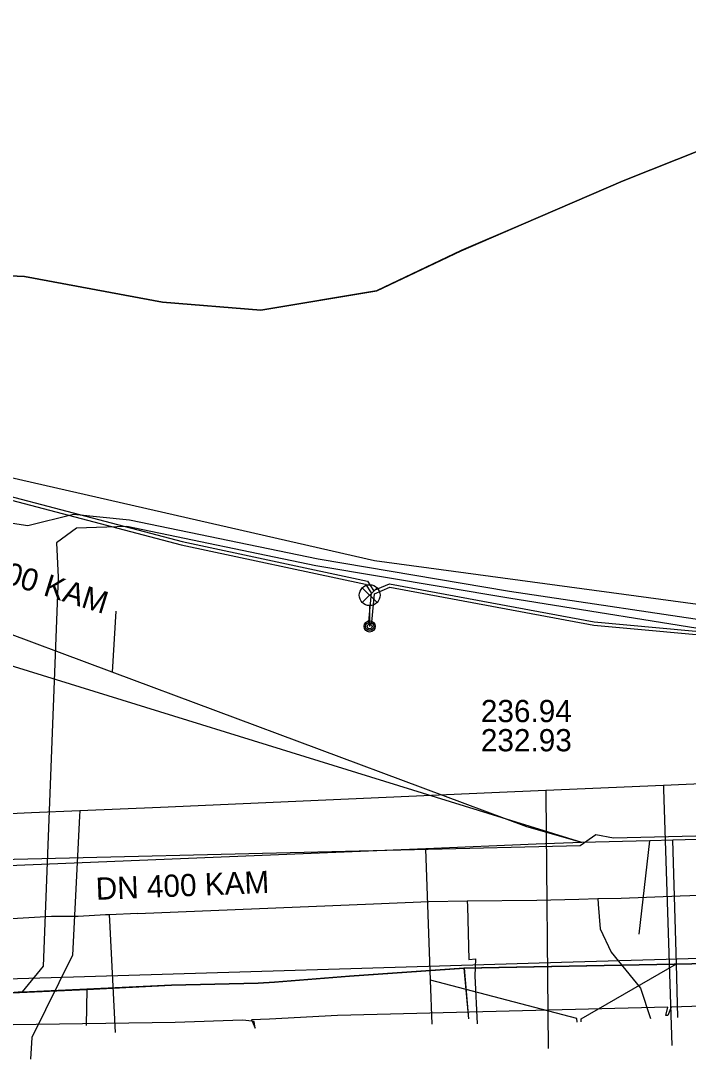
# Model space of a CAD drawing. Extents: x -595540 to -593988, y -1160850 to -1159202.
# Drawn here: x -594932.45 to -594908.44, y -1160782.42 to -1160745.06 of the extents above; entities that cross this region are included whole.
import ezdxf

# ---------------------------------------------------------------- set-up
doc = ezdxf.new("R2010")
doc.units = 0
for name, color, linetype in [('BKOM-ODVODNENI_trasa sítě', 7, 'Continuous'), ('BVK-JEDNOTNA_popisy', 7, 'Continuous'), ('BVK-JEDNOTNA_trasa sítě', 7, 'Continuous'), ('BVK-KANALIZACE_ vyřazená trasa sítě', 7, 'Continuous'), ('BVK-VODOVOD_trasa sítě', 7, 'Continuous'), ('BVK-VODOVOD_trasa zrušené sítě', 7, 'Continuous'), ('CETIN_kabel podzemní', 7, 'Continuous'), ('DESTOVA_trasa neprovozované sítě', 7, 'Continuous'), ('DSP-SDEL-VODAFONE_kabel', 7, 'Continuous'), ('EON-NN_kabel', 7, 'Continuous'), ('EON-VN_kabel', 7, 'Continuous'), ('INNOGY-STL_trasa sítě', 7, 'Continuous'), ('JEDNOTNA_trasa neprovozované sítě', 7, 'Continuous'), ('TSB_kabel VO', 7, 'Continuous'), ('TSB_lampy VO', 7, 'Continuous')]:
    doc.layers.add(name, color=color, linetype=linetype)

msp = doc.modelspace()

# ---------------------------------------------------------------- linework, layer by layer
at = {"layer": 'BKOM-ODVODNENI_trasa sítě'}
msp.add_lwpolyline([(-594910.2, -1160777.92), (-594909.817, -1160774.559)], dxfattribs=at)
at = {"layer": 'BVK-JEDNOTNA_popisy'}
msp.add_line((-594915.9, -1160770.417), (-594915.9, -1160770.417), dxfattribs=at)
at = {"layer": 'BVK-JEDNOTNA_trasa sítě'}
for points in [[(-594912.273, -1160774.624), (-594938.769, -1160766.417), (-594951.138, -1160762.587), (-594956.75, -1160760.85)], [(-594869.804, -1160773.507), (-594873.738, -1160773.61), (-594874.61, -1160773.633), (-594878.19, -1160773.728), (-594884.02, -1160773.881), (-594885.041, -1160773.908), (-594892.812, -1160774.112), (-594903.717, -1160774.399), (-594908.994, -1160774.538), (-594909.817, -1160774.559), (-594912.273, -1160774.624)], [(-594912.273, -1160774.624), (-594913.908, -1160774.683), (-594917.874, -1160774.85), (-594935.248, -1160775.554), (-594938.697, -1160775.692), (-594939.571, -1160775.728), (-594941.692, -1160775.813)]]:
    msp.add_lwpolyline(points, dxfattribs=at)
at = {"layer": 'BVK-KANALIZACE_ vyřazená trasa sítě'}
msp.add_line((-594929.03, -1160766.3), (-594929.167, -1160768.492), dxfattribs=at)
for points in [[(-594912.273, -1160774.624), (-594914.244, -1160774.053), (-594929.167, -1160768.492), (-594938.554, -1160764.996), (-594948.512, -1160761.285), (-594951.232, -1160760.272)], [(-594869.699, -1160773.46), (-594911.123, -1160774.466), (-594911.762, -1160774.34)], [(-594911.762, -1160774.34), (-594912.332, -1160774.739), (-594936.179, -1160775.32)]]:
    msp.add_lwpolyline(points, dxfattribs=at)
at = {"layer": 'BVK-VODOVOD_trasa sítě'}
for points in [[(-594875.78, -1160771.11), (-594879.52, -1160771.27), (-594880.35, -1160771.31), (-594885.83, -1160771.55), (-594891.69, -1160771.8), (-594894.1, -1160771.91), (-594896.86, -1160772.03), (-594897.67, -1160772.06), (-594903.61, -1160772.32), (-594909.33, -1160772.57), (-594913.56, -1160772.75), (-594915.51, -1160772.84), (-594921.48, -1160773.1), (-594927.42, -1160773.36), (-594930.33, -1160773.48), (-594932.06, -1160773.56), (-594935.46, -1160773.71), (-594935.76, -1160773.72)], [(-594913.56, -1160772.75), (-594913.56, -1160772.9), (-594913.48, -1160782.03)], [(-594909.33, -1160772.57), (-594909.33, -1160772.7), (-594909.03, -1160781.93)], [(-594930.33, -1160773.48), (-594930.34, -1160773.67), (-594930.59, -1160778.67), (-594932.052, -1160781.638), (-594932.1, -1160782.418)]]:
    msp.add_lwpolyline(points, dxfattribs=at)
at = {"layer": 'BVK-VODOVOD_trasa zrušené sítě'}
msp.add_lwpolyline([(-594937.054, -1160779.34), (-594937.071, -1160779.648), (-594936.613, -1160779.634), (-594931.361, -1160779.477), (-594913.001, -1160778.927), (-594909.231, -1160778.814), (-594895.813, -1160778.413), (-594892.17, -1160778.304), (-594879.821, -1160777.934), (-594879.469, -1160777.923), (-594875.52, -1160777.778), (-594865.11, -1160777.493), (-594857.269, -1160777.258), (-594850.43, -1160777.053), (-594849.217, -1160777.017), (-594840.994, -1160776.771), (-594839.675, -1160776.732), (-594826.216, -1160776.329), (-594818.306, -1160776.092), (-594815.474, -1160776.007), (-594804.299, -1160775.672), (-594801.425, -1160775.476), (-594800.948, -1160775.379), (-594799.195, -1160774.938)], dxfattribs=at)
at = {"layer": 'CETIN_kabel podzemní'}
for points in [[(-594895.23, -1160720.37), (-594899.75, -1160734.09), (-594904.07, -1160746.78), (-594904.7, -1160747.94), (-594905.92, -1160748.89), (-594910.78, -1160750.82), (-594914.36, -1160752.37), (-594916.61, -1160753.33), (-594919.65, -1160754.78), (-594923.82, -1160755.47), (-594927.35, -1160755.18), (-594932.31, -1160754.26), (-594936.32, -1160754.08), (-594936.74, -1160754.26), (-594937.69, -1160756.31), (-594938.49, -1160759.33), (-594938.98, -1160760.4), (-594939.13, -1160760.57), (-594944.88, -1160758.83), (-594949.88, -1160756.96), (-594958.59, -1160753.03)], [(-594907.05, -1160778.96), (-594916.51, -1160779.14)], [(-594916.51, -1160779.14), (-594920.62, -1160779.43), (-594923.32, -1160779.65), (-594923.91, -1160779.68), (-594927.03, -1160779.75), (-594930.07, -1160779.9)], [(-594916.51, -1160779.14), (-594916.34, -1160780.97)], [(-594930.07, -1160779.9), (-594936.26, -1160780.19), (-594938.27, -1160779.7), (-594941.61, -1160779.83), (-594944.66, -1160779.93)], [(-594930.07, -1160779.9), (-594930.1, -1160781.2)]]:
    msp.add_lwpolyline(points, dxfattribs=at)
at = {"layer": 'DESTOVA_trasa neprovozované sítě'}
msp.add_line((-594910.2, -1160777.92), (-594909.817, -1160774.559), dxfattribs=at)
for points in [[(-594912.295, -1160781.078), (-594912.293, -1160780.959), (-594908.866, -1160778.981)], [(-594912.438, -1160781.081), (-594912.45, -1160780.95), (-594917.71, -1160779.574)]]:
    msp.add_lwpolyline(points, dxfattribs=at)
at = {"layer": 'DSP-SDEL-VODAFONE_kabel'}
for p, q in [((-594923.32, -1160779.645), (-594920.622, -1160779.426)), ((-594916.505, -1160779.14), (-594916.354, -1160780.821)), ((-594927.031, -1160779.755), (-594923.907, -1160779.676)), ((-594923.907, -1160779.676), (-594923.32, -1160779.645)), ((-594930.068, -1160779.904), (-594930.102, -1160781.2))]:
    msp.add_line(p, q, dxfattribs=at)
for points in [[(-594938.488, -1160759.33), (-594937.687, -1160756.308), (-594936.74, -1160754.258), (-594936.322, -1160754.083), (-594932.311, -1160754.259), (-594927.352, -1160755.184), (-594923.818, -1160755.468), (-594919.646, -1160754.777), (-594916.614, -1160753.334), (-594914.364, -1160752.368), (-594910.783, -1160750.823), (-594905.922, -1160748.887), (-594904.703, -1160747.939), (-594904.067, -1160746.78), (-594899.752, -1160734.092), (-594895.232, -1160720.373)], [(-594920.622, -1160779.426), (-594916.505, -1160779.14), (-594907.052, -1160778.961), (-594904.043, -1160778.964), (-594900.222, -1160778.658), (-594895.653, -1160778.692), (-594891.744, -1160778.513), (-594881.932, -1160778.17)], [(-594941.607, -1160779.832), (-594938.271, -1160779.704), (-594936.26, -1160780.191), (-594930.068, -1160779.904), (-594927.031, -1160779.755)]]:
    msp.add_lwpolyline(points, dxfattribs=at)
at = {"layer": 'EON-NN_kabel'}
for points in [[(-594924.124, -1160781.052), (-594924.47, -1160781.01), (-594926.89, -1160781.1), (-594936.071, -1160781.233), (-594936.058, -1160781.664), (-594936.258, -1160781.67), (-594936.458, -1160781.676), (-594936.471, -1160781.238), (-594936.58, -1160781.24), (-594939.38, -1160781.255), (-594939.43, -1160779.153), (-594940.36, -1160772.875), (-594940.37, -1160770.411), (-594941.236, -1160769.85), (-594941.104, -1160769.351), (-594939.076, -1160763.186), (-594938.234, -1160760.23), (-594938.802, -1160760.034), (-594944.719, -1160757.99), (-594947.541, -1160756.987), (-594949.413, -1160756.455), (-594955.16, -1160753.921), (-594955.839, -1160753.578), (-594955.533, -1160752.952)], [(-594906.59, -1160766.27), (-594919.73, -1160764.49), (-594933.23, -1160761.41), (-594938.672, -1160759.656), (-594944.586, -1160757.612), (-594947.992, -1160756.462), (-594947.601, -1160755.445), (-594948.103, -1160755.221), (-594948.143, -1160755.335), (-594948.256, -1160755.622), (-594948.08, -1160755.71), (-594948.345, -1160756.368), (-594949.277, -1160756.078), (-594954.28, -1160753.872), (-594954.252, -1160753.525), (-594954.579, -1160753.735), (-594954.989, -1160753.56), (-594955.306, -1160753.399), (-594955.176, -1160753.133)], [(-594874.32, -1160779.5), (-594875.033, -1160779.44), (-594879.561, -1160779.511), (-594879.602, -1160779.741), (-594879.629, -1160779.95), (-594879.702, -1160779.95), (-594879.683, -1160779.514), (-594894.741, -1160779.94), (-594894.5, -1160780.366), (-594894.597, -1160780.37), (-594894.861, -1160779.944), (-594901.474, -1160780.295), (-594901.528, -1160780.588), (-594901.595, -1160780.596), (-594901.593, -1160780.3), (-594909.052, -1160780.543), (-594909.179, -1160780.84), (-594909.247, -1160780.842), (-594909.176, -1160780.546), (-594921.055, -1160780.846), (-594923.501, -1160780.971), (-594924.146, -1160780.999), (-594924.124, -1160781.052)], [(-594924.124, -1160781.052), (-594924.02, -1160781.301), (-594924.06, -1160781.06), (-594924.124, -1160781.052)]]:
    msp.add_lwpolyline(points, dxfattribs=at)
at = {"layer": 'EON-VN_kabel'}
for points in [[(-594936.2, -1160762.61), (-594932.2, -1160763.22), (-594930.55, -1160762.81), (-594928.54, -1160763.01), (-594921.75, -1160764.42), (-594914.87, -1160765.58), (-594906.82, -1160766.78), (-594899.34, -1160767.22), (-594889.38, -1160767.35), (-594875.36, -1160766.99)], [(-594875.39, -1160767.22), (-594889.34, -1160767.51), (-594899.32, -1160767.54), (-594906.82, -1160767.13), (-594914.89, -1160765.83), (-594921.84, -1160764.67), (-594928.63, -1160763.25), (-594930.45, -1160763.32), (-594931.16, -1160763.84), (-594931.105, -1160765.083), (-594931.649, -1160779.07), (-594932.397, -1160779.995), (-594936.47, -1160780.325)]]:
    msp.add_lwpolyline(points, dxfattribs=at)
at = {"layer": 'INNOGY-STL_trasa sítě'}
for points in [[(-594928.245, -1160777.18), (-594919.762, -1160776.826), (-594917.777, -1160776.749), (-594916.389, -1160776.724), (-594913.889, -1160776.699), (-594912.378, -1160776.66), (-594911.693, -1160776.642), (-594910.858, -1160776.621), (-594908.726, -1160776.537), (-594908.385, -1160776.528), (-594905.624, -1160776.458), (-594904.839, -1160777.239), (-594904.046, -1160777.189), (-594902.065, -1160777.141), (-594900.409, -1160777.053), (-594896.121, -1160776.923), (-594892.145, -1160776.735), (-594891.857, -1160776.721), (-594886.017, -1160776.442), (-594884.037, -1160776.363), (-594882.602, -1160776.298), (-594882.305, -1160776.287), (-594881.235, -1160776.269), (-594877.615, -1160776.166)], [(-594916.389, -1160776.724), (-594916.384, -1160776.924), (-594916.338, -1160778.831), (-594916.086, -1160778.809)], [(-594911.693, -1160776.642), (-594911.677, -1160776.841), (-594911.607, -1160777.724), (-594911.215, -1160778.564), (-594910.162, -1160779.864), (-594909.795, -1160780.955)], [(-594928.245, -1160777.18), (-594929.267, -1160777.223), (-594929.403, -1160777.228), (-594930.379, -1160777.284), (-594931.097, -1160777.289), (-594931.343, -1160777.288), (-594932.969, -1160777.384), (-594933.372, -1160777.377), (-594935.337, -1160777.439), (-594935.642, -1160777.439)], [(-594929.267, -1160777.223), (-594929.257, -1160777.423), (-594929.051, -1160781.453)], [(-594916.02, -1160781.14), (-594916.11, -1160779.42), (-594916.086, -1160778.809)]]:
    msp.add_lwpolyline(points, dxfattribs=at)
at = {"layer": 'JEDNOTNA_trasa neprovozované sítě'}
for points in [[(-594908.811, -1160780.912), (-594908.866, -1160778.981), (-594908.994, -1160774.538)], [(-594917.655, -1160781.16), (-594917.71, -1160779.574), (-594917.874, -1160774.85)]]:
    msp.add_lwpolyline(points, dxfattribs=at)
at = {"layer": 'TSB_kabel VO'}
for points in [[(-594960.962, -1160749.196), (-594961.234, -1160749.502), (-594961.632, -1160750.685), (-594961.412, -1160751.238), (-594955.624, -1160754.466), (-594947.358, -1160757.854), (-594945.703, -1160758.452), (-594944.394, -1160758.762), (-594937.883, -1160760.881), (-594937.508, -1160760.941), (-594926.646, -1160763.792), (-594919.973, -1160765.217), (-594919.757, -1160765.555), (-594919.187, -1160765.318), (-594911.822, -1160766.681), (-594901.376, -1160767.64), (-594895.647, -1160767.84), (-594883.2, -1160768.76), (-594881.163, -1160768.61), (-594878.423, -1160768.506), (-594877.437, -1160767.931)], [(-594961.508, -1160751.322), (-594955.676, -1160754.574), (-594947.402, -1160757.966), (-594945.737, -1160758.568), (-594944.426, -1160758.878), (-594938.129, -1160760.927), (-594937.968, -1160760.979), (-594938.275, -1160762.29), (-594938.335, -1160762.438), (-594938.165, -1160762.35), (-594937.852, -1160761.007), (-594937.532, -1160761.059), (-594926.674, -1160763.908), (-594920.047, -1160765.323), (-594919.842, -1160765.645), (-594919.941, -1160766.684), (-594919.894, -1160766.83), (-594919.821, -1160766.695), (-594919.724, -1160765.672), (-594919.173, -1160765.442), (-594911.838, -1160766.799), (-594901.445, -1160767.754)]]:
    msp.add_lwpolyline(points, dxfattribs=at)
at = {"layer": 'TSB_lampy VO'}
for p, q in [((-594920.165, -1160765.99), (-594919.635, -1160765.46)), ((-594920.165, -1160765.46), (-594919.635, -1160765.99)), ((-594920.165, -1160765.99), (-594919.635, -1160765.46)), ((-594920.165, -1160765.46), (-594919.635, -1160765.99)), ((-594919.9, -1160766.1), (-594919.9, -1160766.85)), ((-594919.9, -1160766.1), (-594919.9, -1160766.85))]:
    msp.add_line(p, q, dxfattribs=at)
for centre, radius in [((-594919.9, -1160765.725), 0.375), ((-594919.9, -1160765.725), 0.375), ((-594919.9, -1160766.85), 0.2), ((-594919.9, -1160766.85), 0.2), ((-594919.9, -1160766.85), 0.145), ((-594919.9, -1160766.85), 0.145), ((-594919.9, -1160766.85), 0.0876), ((-594919.9, -1160766.85), 0.0876)]:
    msp.add_circle(centre, radius, dxfattribs=at)

# ---------------------------------------------------------------- texts
at = {"layer": 'BVK-JEDNOTNA_popisy'}
for rotation, p in [(342.7964, (-594935.426, -1160764.558)), (2.3147, (-594929.737, -1160776.687))]:
    msp.add_text('DN 400 KAM', height=0.8, rotation=rotation, dxfattribs=at).set_placement(p)
for s, p in [('236.94', (-594915.9, -1160770.292)), ('232.93', (-594915.9, -1160771.342))]:
    msp.add_text(s, height=0.8, dxfattribs=at).set_placement(p)

doc.saveas('drawing.dxf')
